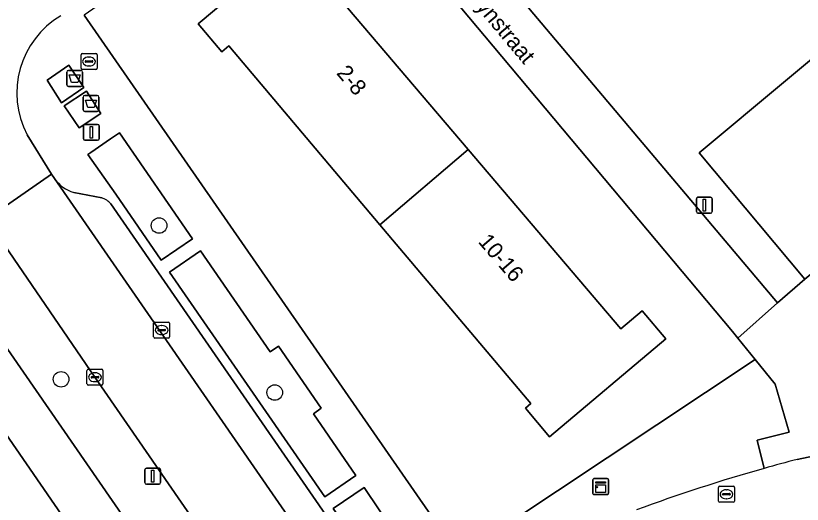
# Model space of a CAD drawing. Extents: x 159888 to 160761, y 384031 to 384750.
# Drawn here: x 160370.36 to 160419.72, y 384154.38 to 384185.06 of the extents above; entities that cross this region are included whole.
import ezdxf

# ---------------------------------------------------------------- set-up
doc = ezdxf.new("R2010")
doc.units = 0
for name, color, linetype in [('IMGEO_Afval_apart_plaats', 7, 'Continuous'), ('IMGEO_Berm_groen', 7, 'Continuous'), ('IMGEO_Boom', 7, 'Continuous'), ('IMGEO_Brandkraan', 7, 'Continuous'), ('IMGEO_Erf', 7, 'Continuous'), ('IMGEO_Fietspad_gesloten', 7, 'Continuous'), ('IMGEO_Groenvoorziening', 7, 'Continuous'), ('IMGEO_Kast', 7, 'Continuous'), ('IMGEO_Kolk', 7, 'Continuous'), ('IMGEO_Lichtmast', 7, 'Continuous'), ('IMGEO_Openbare_ruimte_label', 7, 'Continuous'), ('IMGEO_Pand', 7, 'Continuous'), ('IMGEO_Pand_nummerreeks', 7, 'Continuous'), ('IMGEO_Parkeervlak_open', 7, 'Continuous'), ('IMGEO_Rijbaan_lokaal_open', 7, 'Continuous'), ('IMGEO_Voetpad_gesloten', 7, 'Continuous'), ('IMGEO_Voetpad_open', 7, 'Continuous')]:
    doc.layers.add(name, color=color, linetype=linetype)

msp = doc.modelspace()

# ---------------------------------------------------------------- linework, layer by layer
at = {"layer": 'IMGEO_Afval_apart_plaats'}
for p, q in [((160373.661, 384181.629), (160374.451, 384181.629)), ((160374.451, 384181.629), (160373.661, 384181.629)), ((160373.561, 384180.729), (160373.561, 384181.529)), ((160373.561, 384181.529), (160373.561, 384180.729)), ((160374.551, 384181.529), (160374.551, 384180.729)), ((160374.551, 384180.729), (160374.551, 384181.529)), ((160374.451, 384180.629), (160373.661, 384180.629)), ((160373.661, 384180.629), (160374.451, 384180.629)), ((160374.583, 384179.154), (160374.583, 384179.954)), ((160374.583, 384179.954), (160374.583, 384179.154)), ((160374.683, 384180.054), (160375.473, 384180.054)), ((160375.473, 384180.054), (160374.683, 384180.054)), ((160375.573, 384179.954), (160375.573, 384179.154)), ((160375.573, 384179.154), (160375.573, 384179.954)), ((160375.473, 384179.054), (160374.683, 384179.054)), ((160374.683, 384179.054), (160375.473, 384179.054))]:
    msp.add_line(p, q, dxfattribs=at)
for points in [[(160373.704, 384181.343), (160374.408, 384181.343), (160374.259, 384180.873), (160373.853, 384180.873), (160373.704, 384181.343)], [(160374.726, 384179.768), (160375.43, 384179.768), (160375.281, 384179.298), (160374.875, 384179.298), (160374.726, 384179.768)]]:
    msp.add_lwpolyline(points, dxfattribs=at)
for centre, start, end in [((160373.661, 384181.529), 90, 180), ((160373.661, 384181.529), 90, 180), ((160374.451, 384181.529), 0, 90), ((160374.451, 384181.529), 360, 90), ((160373.661, 384180.729), 180, 270), ((160373.661, 384180.729), 180, 270), ((160374.451, 384180.729), 270, 0), ((160374.451, 384180.729), 270, 0), ((160374.683, 384179.954), 90, 180), ((160374.683, 384179.954), 90, 180), ((160375.473, 384179.954), 0, 90), ((160375.473, 384179.954), 360, 90), ((160374.683, 384179.154), 180, 270), ((160374.683, 384179.154), 180, 270), ((160375.473, 384179.154), 270, 0), ((160375.473, 384179.154), 270, 0)]:
    msp.add_arc(centre, 0.1, start, end, dxfattribs=at)
at = {"layer": 'IMGEO_Berm_groen'}
msp.add_lwpolyline([(160375.33, 384162.358), (160368.516, 384172.281), (160363.339, 384179.819), (160361.603, 384178.668), (160360.859, 384178.175), (160360.492, 384177.637), (160379.582, 384150.01), (160385.517, 384141.168), (160385.525, 384141.156), (160385.76, 384140.807), (160385.806, 384140.847), (160386.901, 384141.797), (160388.539, 384143.217), (160388.361, 384143.475), (160384.755, 384148.698)], close=True, dxfattribs=at)
msp.add_lwpolyline([(160381.089, 384136.417), (160382.45, 384137.684), (160383.579, 384138.735), (160383.338, 384139.04), (160358.061, 384175.74)], dxfattribs=at)
at = {"layer": 'IMGEO_Boom'}
for centre in [(160379.35, 384171.885), (160373.202, 384162.227), (160386.609, 384161.395)]:
    msp.add_circle(centre, 0.489, dxfattribs=at)
at = {"layer": 'IMGEO_Brandkraan'}
for p, q in [((160374.457, 384181.761), (160374.457, 384182.613)), ((160374.532, 384182.687), (160375.384, 384182.687)), ((160375.458, 384182.613), (160375.458, 384181.761)), ((160374.716, 384182.181), (160374.716, 384182.193)), ((160375.154, 384182.144), (160374.756, 384182.144)), ((160374.759, 384182.23), (160375.157, 384182.23)), ((160374.945, 384182.467), (160374.97, 384182.467)), ((160375.2, 384182.193), (160375.2, 384182.181)), ((160375.384, 384181.687), (160374.532, 384181.687)), ((160374.968, 384181.907), (160374.943, 384181.907)), ((160414.533, 384155.505), (160415.385, 384155.505)), ((160414.458, 384154.579), (160414.458, 384155.431)), ((160414.717, 384154.999), (160414.717, 384155.011)), ((160415.155, 384154.962), (160414.757, 384154.962)), ((160414.76, 384155.048), (160415.158, 384155.048)), ((160414.946, 384155.285), (160414.971, 384155.285)), ((160415.201, 384155.011), (160415.201, 384154.999)), ((160415.459, 384155.431), (160415.459, 384154.579)), ((160415.385, 384154.505), (160414.533, 384154.505)), ((160414.969, 384154.725), (160414.944, 384154.725))]:
    msp.add_line(p, q, dxfattribs=at)
for points in [[(160374.457, 384181.761), (160374.457, 384182.613)], [(160374.532, 384182.687), (160375.384, 384182.687)], [(160375.458, 384182.613), (160375.458, 384181.761)], [(160375.384, 384181.687), (160374.532, 384181.687)], [(160414.533, 384155.505), (160415.385, 384155.505)], [(160414.458, 384154.579), (160414.458, 384155.431)], [(160415.459, 384155.431), (160415.459, 384154.579)], [(160415.385, 384154.505), (160414.533, 384154.505)]]:
    msp.add_lwpolyline(points, dxfattribs=at)
for centre, radius, start, end in [((160374.534, 384182.611), 0.0765, 91.552, 178.448), ((160374.534, 384182.611), 0.0765, 91.552, 178.448), ((160375.382, 384182.611), 0.0765, 1.552, 88.448), ((160375.382, 384182.611), 0.0765, 1.552, 88.448), ((160374.756, 384182.19), 0.0403, 85.8775, 175.7526), ((160374.753, 384182.18), 0.0366, 178.938, 274.7102), ((160375.157, 384182.187), 0.043, 264.8664, 352.4533), ((160375.161, 384182.192), 0.0386, 1.7309, 96.639), ((160374.534, 384181.763), 0.0765, 181.552, 268.448), ((160374.534, 384181.763), 0.0765, 181.552, 268.448), ((160375.382, 384181.763), 0.0765, 271.552, 358.448), ((160375.382, 384181.763), 0.0765, 271.552, 358.448), ((160414.535, 384155.429), 0.0765, 91.552, 178.448), ((160414.535, 384155.429), 0.0765, 91.552, 178.448), ((160415.383, 384155.429), 0.0765, 1.552, 88.448), ((160415.383, 384155.429), 0.0765, 1.552, 88.448), ((160414.757, 384155.008), 0.0403, 85.8775, 175.7526), ((160414.754, 384154.998), 0.0366, 178.938, 274.7102), ((160415.158, 384155.005), 0.043, 264.8664, 352.4533), ((160415.162, 384155.01), 0.0386, 1.7309, 96.639), ((160414.535, 384154.581), 0.0765, 181.552, 268.448), ((160414.535, 384154.581), 0.0765, 181.552, 268.448), ((160415.383, 384154.581), 0.0765, 271.552, 358.448), ((160415.383, 384154.581), 0.0765, 271.552, 358.448)]:
    msp.add_arc(centre, radius, start, end, dxfattribs=at)
for centre, major_axis, ratio, start_param, end_param in [((160374.944, 384182.187), (-0.387, 0.002), 0.722429, 4.712389, 7.853982), ((160374.969, 384182.187), (-0.39, 0.002), 0.717154, 1.570796, 4.712389), ((160414.945, 384155.005), (-0.387, 0.002), 0.722429, 4.712389, 7.853982), ((160414.97, 384155.005), (-0.39, 0.002), 0.717154, 1.570796, 4.712389)]:
    msp.add_ellipse(centre, major_axis=major_axis, ratio=ratio, start_param=start_param, end_param=end_param, dxfattribs=at)
at = {"layer": 'IMGEO_Erf'}
for points in [[(160445.745, 384203.546), (160456.575, 384212.575), (160467.421, 384221.617), (160468.175, 384222.224), (160462.762, 384230.216), (160419.38, 384194.033), (160413.229, 384188.902), (160401.999, 384190.089), (160403.03, 384199.875), (160396.267, 384200.587), (160392.322, 384197.688), (160392.679, 384197.264), (160418.154, 384167.028), (160419.883, 384168.51), (160413.255, 384176.46), (160424.085, 384185.489), (160434.915, 384194.518)], [(160416.754, 384163.478), (160415.675, 384164.808), (160415.333, 384165.23), (160390.189, 384195.245), (160389.837, 384195.662), (160374.65, 384185.092), (160396.428, 384153.672), (160398.179, 384151.117)], [(160398.757, 384176.656), (160408.329, 384165.398), (160409.667, 384166.525), (160411.148, 384164.766), (160403.853, 384158.617), (160402.339, 384160.413), (160402.678, 384160.699), (160393.207, 384171.937), (160383.736, 384183.175), (160383.291, 384182.8), (160381.81, 384184.558), (160389.098, 384190.7), (160390.568, 384188.957), (160389.246, 384187.843)]]:
    msp.add_lwpolyline(points, close=True, dxfattribs=at)
at = {"layer": 'IMGEO_Fietspad_gesloten'}
msp.add_lwpolyline([(160300.173, 384259.725), (160301.925, 384257.178), (160328.105, 384219.124), (160330.579, 384215.605), (160356.471, 384178.065), (160358.061, 384175.74), (160383.338, 384139.04), (160385.76, 384140.807), (160385.525, 384141.156), (160385.517, 384141.168), (160379.582, 384150.01), (160360.492, 384177.637)], dxfattribs=at)
at = {"layer": 'IMGEO_Groenvoorziening'}
for points in [[(160376.871, 384177.707), (160376.296, 384177.326), (160375.07, 384176.482), (160374.886, 384176.356), (160376.64, 384173.85), (160379.494, 384169.705), (160381.442, 384171.042)], [(160389.745, 384154.85), (160391.704, 384156.182), (160389.05, 384160.063), (160389.522, 384160.41), (160386.839, 384164.302), (160386.334, 384163.961), (160381.96, 384170.29), (160380.009, 384168.963)], [(160392.216, 384155.422), (160390.276, 384154.105), (160395.116, 384147.175), (160396.939, 384148.42)]]:
    msp.add_lwpolyline(points, close=True, dxfattribs=at)
msp.add_lwpolyline([(160417.322, 384156.63), (160416.894, 384158.409), (160418.889, 384158.907), (160418.01, 384161.931), (160416.754, 384163.478), (160398.179, 384151.117), (160399.463, 384149.243)], dxfattribs=at)
msp.add_arc((160446.869, 384052.148), 108.579, 105.79056, 110.24135, dxfattribs=at)
at = {"layer": 'IMGEO_Kast'}
for p, q in [((160406.64, 384155.987), (160407.481, 384155.987)), ((160407.481, 384155.987), (160406.64, 384155.987)), ((160406.565, 384155.062), (160406.565, 384155.903)), ((160406.565, 384155.903), (160406.565, 384155.062)), ((160407.565, 384155.912), (160407.565, 384155.071)), ((160407.565, 384155.071), (160407.565, 384155.912)), ((160407.49, 384154.987), (160406.649, 384154.987)), ((160406.649, 384154.987), (160407.49, 384154.987))]:
    msp.add_line(p, q, dxfattribs=at)
for points in [[(160406.76, 384155.777), (160407.36, 384155.777), (160407.36, 384155.692), (160406.76, 384155.692), (160406.76, 384155.777)], [(160406.76, 384155.602), (160407.36, 384155.602), (160407.36, 384155.113), (160406.76, 384155.113), (160406.76, 384155.602)]]:
    msp.add_lwpolyline(points, dxfattribs=at)
msp.add_circle((160406.844, 384155.451), 0.0377, dxfattribs=at)
for centre, start, end in [((160406.643, 384155.909), 92.4484, 184.2845), ((160406.643, 384155.909), 92.4484, 184.2845), ((160407.487, 384155.909), 2.4484, 94.2845), ((160407.487, 384155.909), 2.4484, 94.2845), ((160406.643, 384155.065), 182.4484, 274.2845), ((160406.643, 384155.065), 182.4484, 274.2845), ((160407.487, 384155.065), 272.4484, 4.2845), ((160407.487, 384155.065), 272.4484, 4.2845)]:
    msp.add_arc(centre, 0.0779, start, end, dxfattribs=at)
at = {"layer": 'IMGEO_Kolk'}
for p, q in [((160379.088, 384165.817), (160379.94, 384165.817)), ((160379.013, 384164.891), (160379.013, 384165.743)), ((160379.272, 384165.311), (160379.272, 384165.323)), ((160379.315, 384165.36), (160379.713, 384165.36)), ((160379.501, 384165.597), (160379.526, 384165.597)), ((160379.756, 384165.323), (160379.756, 384165.311)), ((160380.014, 384165.743), (160380.014, 384164.891)), ((160379.71, 384165.274), (160379.312, 384165.274)), ((160379.524, 384165.037), (160379.499, 384165.037)), ((160379.94, 384164.817), (160379.088, 384164.817)), ((160374.904, 384162.858), (160375.756, 384162.858)), ((160374.829, 384161.932), (160374.829, 384162.784)), ((160375.088, 384162.352), (160375.088, 384162.364)), ((160375.131, 384162.401), (160375.529, 384162.401)), ((160375.317, 384162.638), (160375.342, 384162.638)), ((160375.572, 384162.364), (160375.572, 384162.352)), ((160375.83, 384162.784), (160375.83, 384161.932)), ((160375.756, 384161.858), (160374.904, 384161.858)), ((160375.526, 384162.315), (160375.128, 384162.315)), ((160375.34, 384162.078), (160375.315, 384162.078))]:
    msp.add_line(p, q, dxfattribs=at)
for points in [[(160379.088, 384165.817), (160379.94, 384165.817)], [(160379.013, 384164.891), (160379.013, 384165.743)], [(160380.014, 384165.743), (160380.014, 384164.891)], [(160379.94, 384164.817), (160379.088, 384164.817)], [(160374.904, 384162.858), (160375.756, 384162.858)], [(160374.829, 384161.932), (160374.829, 384162.784)], [(160375.83, 384162.784), (160375.83, 384161.932)], [(160375.756, 384161.858), (160374.904, 384161.858)]]:
    msp.add_lwpolyline(points, dxfattribs=at)
for centre, radius, start, end in [((160379.09, 384165.741), 0.0765, 91.552, 178.448), ((160379.09, 384165.741), 0.0765, 91.552, 178.448), ((160379.938, 384165.741), 0.0765, 1.552, 88.448), ((160379.938, 384165.741), 0.0765, 1.552, 88.448), ((160379.312, 384165.32), 0.0403, 85.8775, 175.7526), ((160379.309, 384165.31), 0.0366, 178.938, 274.7102), ((160379.713, 384165.317), 0.043, 264.8664, 352.4533), ((160379.717, 384165.322), 0.0386, 1.7309, 96.639), ((160379.09, 384164.893), 0.0765, 181.552, 268.448), ((160379.09, 384164.893), 0.0765, 181.552, 268.448), ((160379.938, 384164.893), 0.0765, 271.552, 358.448), ((160379.938, 384164.893), 0.0765, 271.552, 358.448), ((160374.906, 384162.782), 0.0765, 91.552, 178.448), ((160374.906, 384162.782), 0.0765, 91.552, 178.448), ((160375.754, 384162.782), 0.0765, 1.552, 88.448), ((160375.754, 384162.782), 0.0765, 1.552, 88.448), ((160375.128, 384162.361), 0.0403, 85.8775, 175.7526), ((160375.125, 384162.351), 0.0366, 178.938, 274.7102), ((160375.529, 384162.358), 0.043, 264.8664, 352.4533), ((160375.533, 384162.363), 0.0386, 1.7309, 96.639), ((160374.906, 384161.934), 0.0765, 181.552, 268.448), ((160374.906, 384161.934), 0.0765, 181.552, 268.448), ((160375.754, 384161.934), 0.0765, 271.552, 358.448), ((160375.754, 384161.934), 0.0765, 271.552, 358.448)]:
    msp.add_arc(centre, radius, start, end, dxfattribs=at)
for centre, major_axis, ratio, start_param, end_param in [((160379.5, 384165.317), (-0.387, 0.002), 0.722429, 4.712389, 7.853982), ((160379.525, 384165.317), (-0.39, 0.002), 0.717154, 1.570796, 4.712389), ((160375.316, 384162.358), (-0.387, 0.002), 0.722429, 4.712389, 7.853982), ((160375.341, 384162.358), (-0.39, 0.002), 0.717154, 1.570796, 4.712389)]:
    msp.add_ellipse(centre, major_axis=major_axis, ratio=ratio, start_param=start_param, end_param=end_param, dxfattribs=at)
at = {"layer": 'IMGEO_Lichtmast'}
for p, q in [((160374.703, 384178.239), (160375.493, 384178.239)), ((160375.493, 384178.239), (160374.703, 384178.239)), ((160374.603, 384177.339), (160374.603, 384178.139)), ((160374.603, 384178.139), (160374.603, 384177.339)), ((160375.593, 384178.139), (160375.593, 384177.339)), ((160375.593, 384177.339), (160375.593, 384178.139)), ((160375.493, 384177.239), (160374.703, 384177.239)), ((160374.703, 384177.239), (160375.493, 384177.239)), ((160413.072, 384172.76), (160413.072, 384173.56)), ((160413.072, 384173.56), (160413.072, 384172.76)), ((160413.172, 384173.66), (160413.962, 384173.66)), ((160413.962, 384173.66), (160413.172, 384173.66)), ((160414.062, 384173.56), (160414.062, 384172.76)), ((160414.062, 384172.76), (160414.062, 384173.56)), ((160413.962, 384172.66), (160413.172, 384172.66)), ((160413.172, 384172.66), (160413.962, 384172.66)), ((160378.458, 384155.739), (160378.458, 384156.539)), ((160378.458, 384156.539), (160378.458, 384155.739)), ((160378.558, 384156.639), (160379.348, 384156.639)), ((160379.348, 384156.639), (160378.558, 384156.639)), ((160379.448, 384156.539), (160379.448, 384155.739)), ((160379.448, 384155.739), (160379.448, 384156.539)), ((160379.348, 384155.639), (160378.558, 384155.639)), ((160378.558, 384155.639), (160379.348, 384155.639))]:
    msp.add_line(p, q, dxfattribs=at)
for points in [[(160375.023, 384178.114), (160375.173, 384178.114), (160375.173, 384177.364), (160375.023, 384177.364), (160375.023, 384178.114)], [(160413.492, 384173.535), (160413.642, 384173.535), (160413.642, 384172.785), (160413.492, 384172.785), (160413.492, 384173.535)], [(160378.878, 384156.514), (160379.028, 384156.514), (160379.028, 384155.764), (160378.878, 384155.764), (160378.878, 384156.514)]]:
    msp.add_lwpolyline(points, dxfattribs=at)
for centre, start, end in [((160374.703, 384178.139), 90, 180), ((160374.703, 384178.139), 90, 180), ((160375.493, 384178.139), 0, 90), ((160375.493, 384178.139), 360, 90), ((160374.703, 384177.339), 180, 270), ((160374.703, 384177.339), 180, 270), ((160375.493, 384177.339), 270, 0), ((160375.493, 384177.339), 270, 0), ((160413.172, 384173.56), 90, 180), ((160413.172, 384173.56), 90, 180), ((160413.962, 384173.56), 0, 90), ((160413.962, 384173.56), 360, 90), ((160413.172, 384172.76), 180, 270), ((160413.172, 384172.76), 180, 270), ((160413.962, 384172.76), 270, 0), ((160413.962, 384172.76), 270, 0), ((160378.558, 384156.539), 90, 180), ((160378.558, 384156.539), 90, 180), ((160379.348, 384156.539), 0, 90), ((160379.348, 384156.539), 360, 90), ((160378.558, 384155.739), 180, 270), ((160378.558, 384155.739), 180, 270), ((160379.348, 384155.739), 270, 0), ((160379.348, 384155.739), 270, 0)]:
    msp.add_arc(centre, 0.1, start, end, dxfattribs=at)
at = {"layer": 'IMGEO_Pand'}
for points in [[(160393.207, 384171.937), (160398.757, 384176.656), (160389.246, 384187.843), (160390.568, 384188.957), (160389.098, 384190.7), (160381.81, 384184.558), (160383.291, 384182.8), (160383.736, 384183.175)], [(160430.713, 384177.539), (160424.085, 384185.489), (160413.255, 384176.46), (160419.883, 384168.51)], [(160393.207, 384171.937), (160402.678, 384160.699), (160402.339, 384160.413), (160403.853, 384158.617), (160411.148, 384164.766), (160409.667, 384166.525), (160408.329, 384165.398), (160398.757, 384176.656)]]:
    msp.add_lwpolyline(points, close=True, dxfattribs=at)
at = {"layer": 'IMGEO_Parkeervlak_open'}
for points in [[(160372.786, 384174.83), (160392.514, 384146.283), (160392.881, 384145.769)], [(160375.754, 384173.617), (160374.004, 384173.968)], [(160392.363, 384150.005), (160376.327, 384173.238)]]:
    msp.add_lwpolyline(points, dxfattribs=at)
for centre, radius, start, end in [((160374.593, 384176.091), 2.204, 214.9218, 254.5028), ((160375.399, 384172.458), 1.213, 40.0624, 72.9738)]:
    msp.add_arc(centre, radius, start, end, dxfattribs=at)
at = {"layer": 'IMGEO_Rijbaan_lokaal_open'}
msp.add_lwpolyline([(160362.153, 384190.382), (160361.579, 384191.179), (160357.438, 384188.412), (160361.72, 384182.176), (160363.339, 384179.819), (160368.516, 384172.281), (160372.598, 384175.107), (160371.071, 384177.577)], dxfattribs=at)
msp.add_lwpolyline([(160372.786, 384174.83), (160372.598, 384175.107), (160368.516, 384172.281), (160375.33, 384162.358), (160384.755, 384148.698), (160388.361, 384143.475), (160392.514, 384146.283)], close=True, dxfattribs=at)
msp.add_arc((160376.074, 384180.207), 5.652, 120.7378, 207.7315, dxfattribs=at)
at = {"layer": 'IMGEO_Voetpad_gesloten'}
for points in [[(160373.694, 384181.95), (160372.325, 384181.011), (160373.236, 384179.6), (160374.636, 384180.552)], [(160374.8, 384180.331), (160373.388, 384179.411), (160374.346, 384178.025), (160375.705, 384178.915)]]:
    msp.add_lwpolyline(points, close=True, dxfattribs=at)
at = {"layer": 'IMGEO_Voetpad_open'}
for points in [[(160476.095, 384210.002), (160476.352, 384210.26), (160476.585, 384210.54), (160476.617, 384210.587), (160474.049, 384213.667), (160463.203, 384204.625), (160452.373, 384195.596), (160441.543, 384186.568), (160430.713, 384177.539), (160419.883, 384168.51), (160418.154, 384167.028), (160415.675, 384164.808), (160416.754, 384163.478), (160418.01, 384161.931), (160418.889, 384158.907), (160416.894, 384158.409), (160417.322, 384156.63)], [(160392.579, 384146.416), (160395.116, 384147.175), (160390.276, 384154.105), (160392.216, 384155.422), (160396.939, 384148.42), (160398.179, 384151.117), (160396.428, 384153.672), (160374.65, 384185.092)], [(160371.071, 384177.577), (160372.598, 384175.107), (160372.786, 384174.83)], [(160374.004, 384173.968), (160375.754, 384173.617)], [(160376.327, 384173.238), (160392.363, 384150.005)], [(160496.618, 384163.892), (160497, 384163.961), (160497.373, 384164.063), (160497.737, 384164.199), (160498.086, 384164.366), (160498.419, 384164.565), (160498.734, 384164.792), (160499.026, 384165.046), (160499.295, 384165.325), (160499.538, 384165.627), (160499.753, 384165.95), (160499.938, 384166.291), (160500, 384166.424), (160500.142, 384166.785), (160500.252, 384167.157), (160500.317, 384167.486), (160497.469, 384167.144), (160440.695, 384160.33), (160425.801, 384158.542), (160419.388, 384157.193)], [(160419.388, 384157.193), (160425.801, 384158.542), (160425.429, 384158.997), (160431.483, 384164.076), (160431.232, 384164.354)]]:
    msp.add_lwpolyline(points, dxfattribs=at)
for points in [[(160392.679, 384197.264), (160392.322, 384197.688), (160392.025, 384198.09), (160389.416, 384196.161), (160389.837, 384195.662), (160390.189, 384195.245), (160415.333, 384165.23), (160415.675, 384164.808), (160418.154, 384167.028)], [(160373.694, 384181.95), (160374.636, 384180.552), (160373.236, 384179.6), (160372.325, 384181.011)], [(160374.8, 384180.331), (160375.705, 384178.915), (160374.346, 384178.025), (160373.388, 384179.411)], [(160376.871, 384177.707), (160381.442, 384171.042), (160379.494, 384169.705), (160376.64, 384173.85), (160374.886, 384176.356), (160375.07, 384176.482), (160376.296, 384177.326)], [(160380.009, 384168.963), (160381.96, 384170.29), (160386.334, 384163.961), (160386.839, 384164.302), (160389.522, 384160.41), (160389.05, 384160.063), (160391.704, 384156.182), (160389.745, 384154.85)]]:
    msp.add_lwpolyline(points, close=True, dxfattribs=at)
for centre, radius, start, end in [((160376.074, 384180.207), 5.652, 120.7378, 207.7315), ((160374.593, 384176.091), 2.204, 214.9218, 254.5028), ((160375.399, 384172.458), 1.213, 40.0624, 72.9738), ((160445.412, 384057.622), 102.916, 104.64731, 105.83946), ((160445.412, 384057.622), 102.916, 104.64731, 105.83946), ((160446.869, 384052.148), 108.579, 105.79056, 110.24135)]:
    msp.add_arc(centre, radius, start, end, dxfattribs=at)

# ---------------------------------------------------------------- texts
at = {"layer": 'IMGEO_Openbare_ruimte_label'}
msp.add_text('Kapteynstraat', height=1, rotation=309.8863, dxfattribs=at).set_placement((160396.976, 384188.289))
at = {"layer": 'IMGEO_Pand_nummerreeks'}
for s, rotation, p in [('2-8', 310.4497, (160390.439, 384181.438)), ('10-16', 310.6766, (160399.332, 384170.846))]:
    msp.add_text(s, height=1, rotation=rotation, dxfattribs=at).set_placement(p)

doc.saveas('drawing.dxf')
